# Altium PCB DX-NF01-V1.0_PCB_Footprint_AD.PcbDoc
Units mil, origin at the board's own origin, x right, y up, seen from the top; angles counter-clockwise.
Board outline 6000 x 4000 mil, 2 copper layers (Top Layer, Bottom Layer); 1 components, 5 nets, 9 pads, 0 vias.
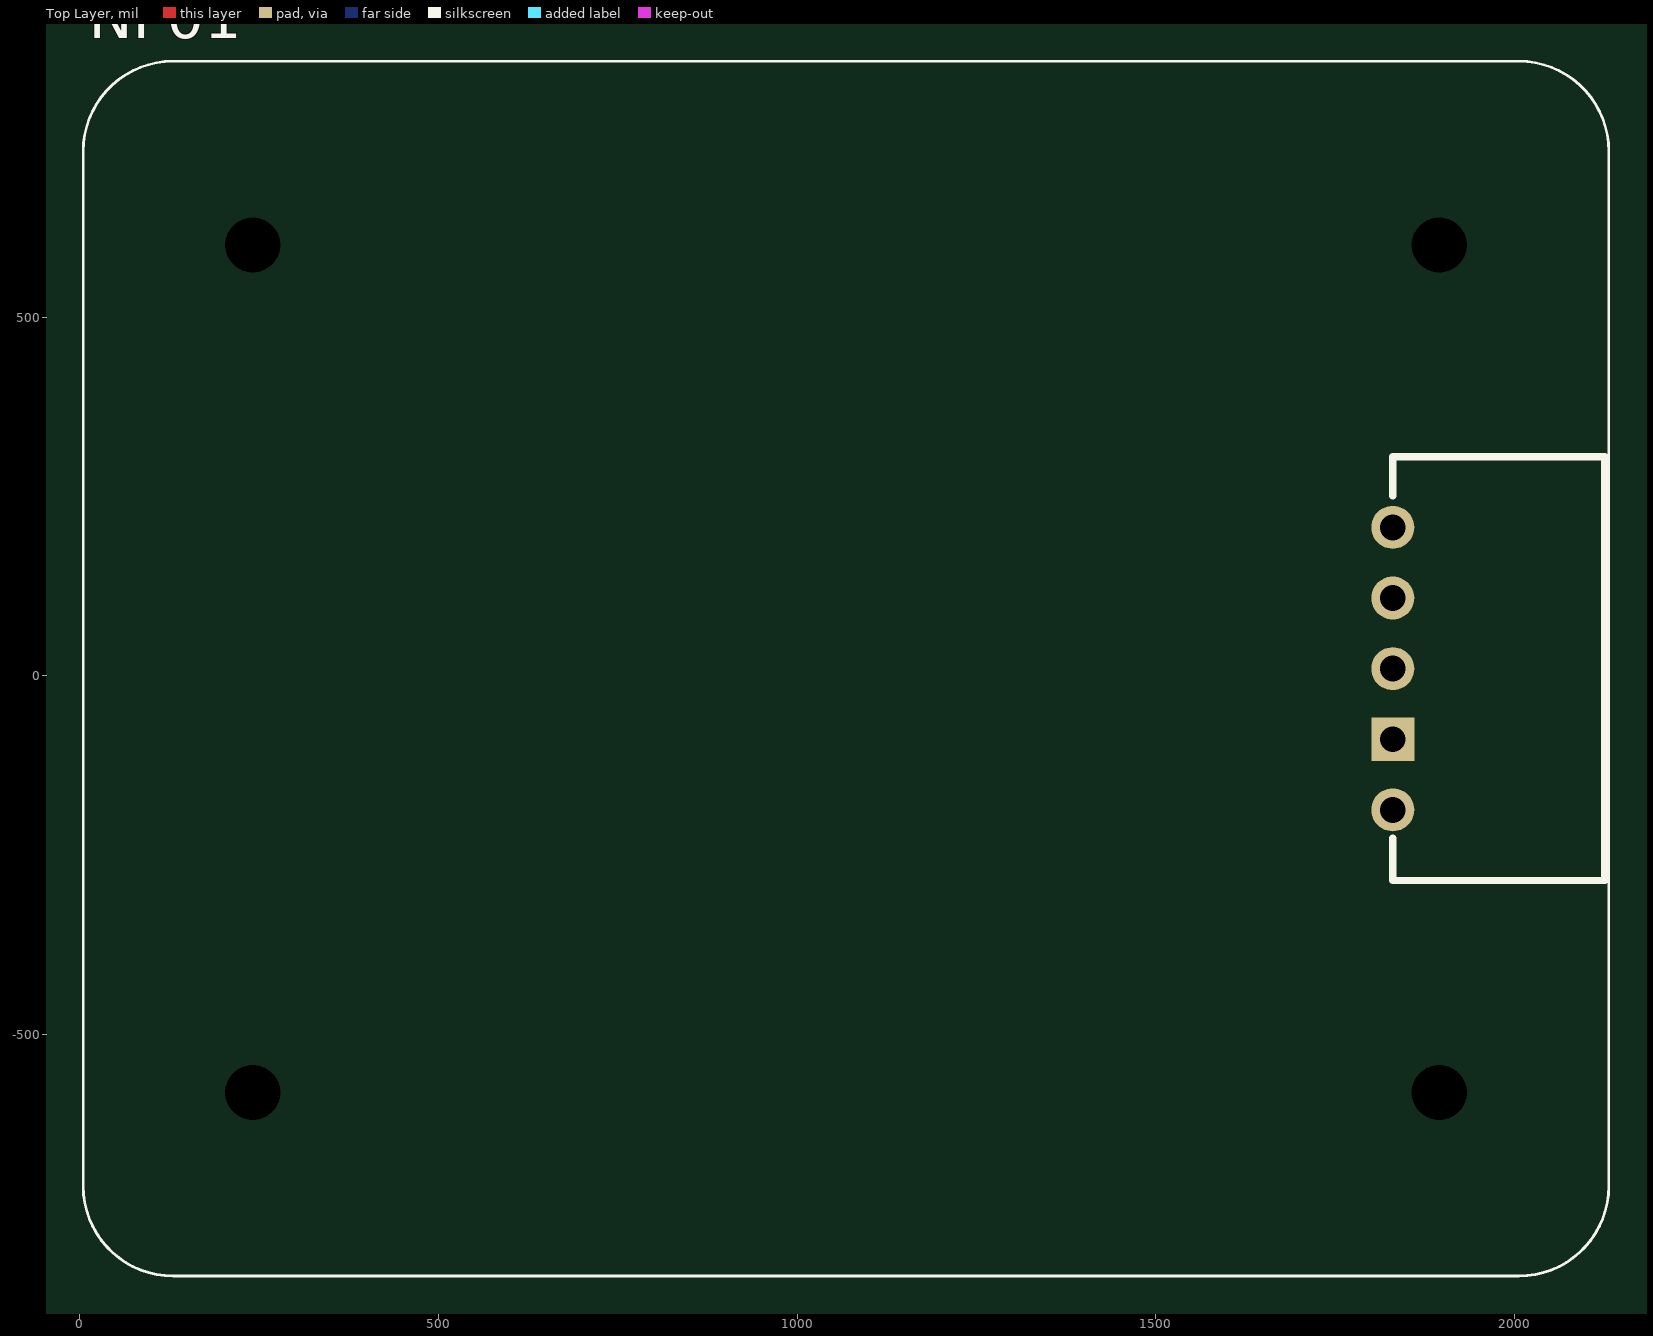
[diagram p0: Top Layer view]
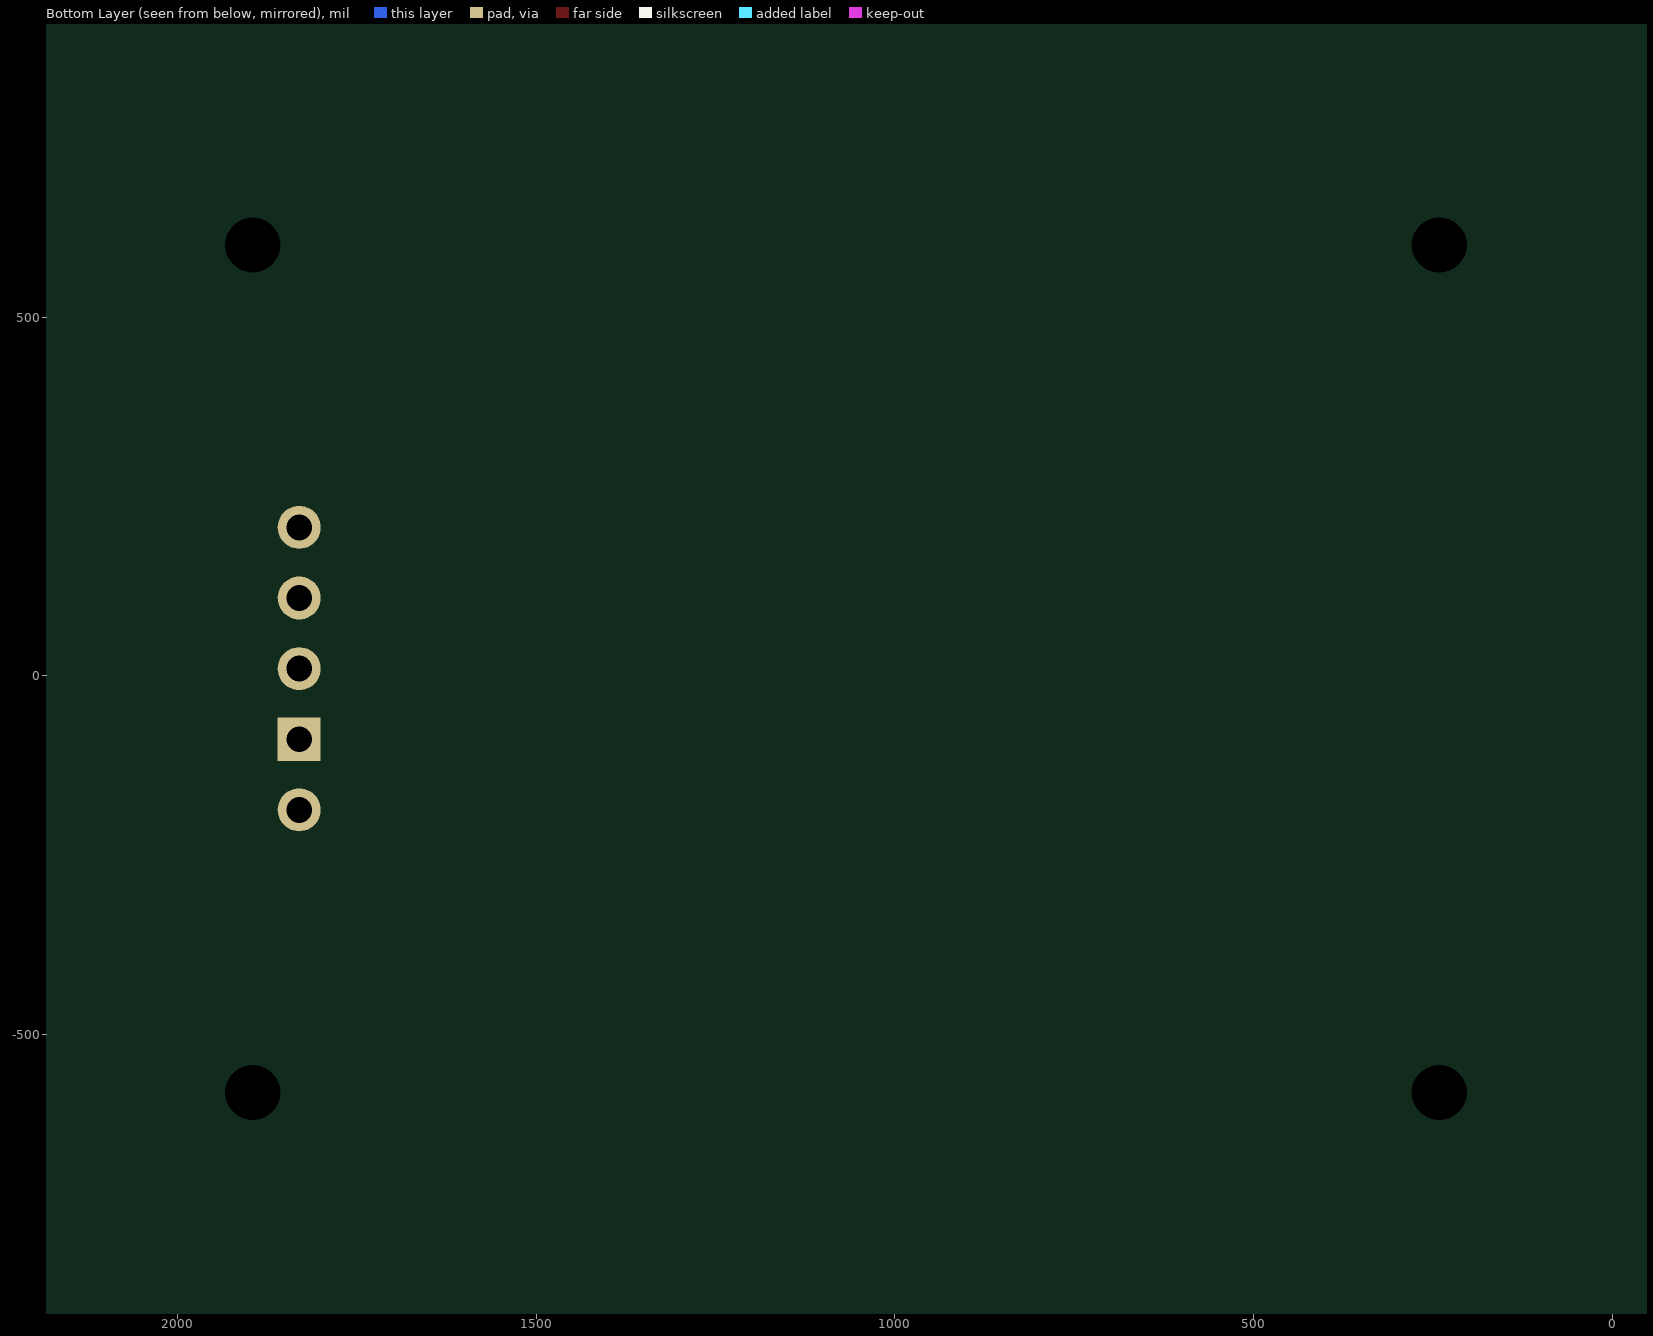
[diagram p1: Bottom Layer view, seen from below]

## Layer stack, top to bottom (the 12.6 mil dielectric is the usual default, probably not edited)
Top Solder: solder mask 0.4, Solder Resist, Dk 3.5
Top Layer: signal copper 1.4
Dielectric 1: dielectric 12.6, FR-4, Dk 4.8
Bottom Layer: signal copper 1.4
Bottom Solder: solder mask 0.4, Solder Resist, Dk 3.5

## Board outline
-1955,-2024.61 4045,-2024.61 4045,1975.39 -1955,1975.39

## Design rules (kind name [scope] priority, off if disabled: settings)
Clearance [All] p1: gap=10 ignorepadtopadclearanceinfootprint=FALSE except(0: Arc-Hole Track-Hole SMDPad-Hole THPad-Hole Via-Hole Fill-Hole Poly-Hole Region-Hole Text-Hole)
PolygonConnect [All] p1: connectstyle=Relief reliefconductorwidth=10 reliefentries=4 polygonreliefangle="90 Angle" airgapwidth=10
RoutingVias [All] p1: holewidth=28 width=50 viastyle="Through Hole" minholewidth=28 minwidth=50 maxholewidth=28 maxwidth=50
SolderMaskExpansion [All] p1: expansion=4 istentingtop=FALSE
Width [All] p1: maxlimit=10 minlimit=10 preferedwidth=10
30 further rules are at their usual default settings.

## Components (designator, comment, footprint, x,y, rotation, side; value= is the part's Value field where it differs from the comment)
NF01 "Comment" NF01 5,10 r0 top

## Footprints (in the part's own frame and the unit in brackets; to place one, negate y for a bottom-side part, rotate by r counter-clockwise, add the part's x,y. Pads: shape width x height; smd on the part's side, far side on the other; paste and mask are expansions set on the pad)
NF01 [mil]
  round 0 hole 76.77 unplated: 1(236.22,-590.55) 1(236.22,590.55) 1(1889.76,-590.55) 1(1889.76,590.55)
  round 60 hole 36: 1(1825,-196.85) 3(1825,0) 4(1825,98.43) 5(1825,196.85)
  rect 60x60 hole 36: 2(1825,-98.42)
  silkscreen extent 0,-846 2126,846

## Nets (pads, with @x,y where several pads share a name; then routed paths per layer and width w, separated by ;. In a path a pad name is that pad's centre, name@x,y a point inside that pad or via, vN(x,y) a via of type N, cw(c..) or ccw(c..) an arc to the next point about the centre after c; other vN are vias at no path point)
C-RX: 
C-TX: 
GND: 
STATUS: 
VIN5V: 
pads on no net: NF01.1 NF01.2 NF01.3 NF01.4 NF01.5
